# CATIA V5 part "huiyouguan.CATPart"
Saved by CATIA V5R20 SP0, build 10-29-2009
Part number: huiyouguan
Material "无"
Bounding box of the stored display mesh (mm): x -24.924 to 17.931, y -271.713 to -24.431, z -40.483 to -8.901
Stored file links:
  C:\Users\Administrator\Desktop\huiyouguan.CATPart
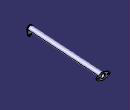
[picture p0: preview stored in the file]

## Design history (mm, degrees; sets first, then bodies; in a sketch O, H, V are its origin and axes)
Body1 (main body), material "无"
  DatumSurface1
  DatumCurve1 to DatumCurve3
  Sketch1 on face of DatumSurface1, origin (-1.5922, -25.6122, 0), H (-0.9981, 0.062, 0), V (0, 0, 1)
    projected circle E1 centre (-13.718, -19.4994) radius 3.1606 from edge of DatumCurve1
    projected circle E2 centre (13.2753, -19.4994) radius 3.1606 from edge of DatumCurve2
    projected circle E3 centre (-0.8655, -19.0792) radius 6.8742 from edge of DatumCurve3
    point P1 (-0.8655, -19.0792)
    point P2 (-13.718, -19.4994)
    point P3 (13.2753, -19.4994)
    arc A1 centre (-0.8655, -19.0792) radius 10.1979 from (1.5838, -9.1798) to (-4.5193, -9.5584) ccw
    arc A2 centre (-13.718, -19.4994) radius 5.9852 from (-15.8625, -13.9115) to (-16.0663, -25.0048) ccw
    arc A3 centre (13.2753, -19.4994) radius 5.9056 from (14.8682, -25.1861) to (15.2155, -13.9217) ccw
    line L1 (-4.5193, -9.5584) -> (-15.8625, -13.9115)
    line L2 (-16.0663, -25.0048) -> (-4.2992, -28.6816)
    line L3 (3.0428, -28.4984) -> (14.8682, -25.1861)
    line L4 (1.5838, -9.1798) -> (15.2155, -13.9217)
    arc A4 centre (-0.8655, -19.0792) radius 10.1979 from (-4.2992, -28.6816) to (3.0428, -28.4984) ccw
    concentricity: P1 E3, P2 E1, P3 E2
    tangency: A2 E3, L1 A2, L3 A3, L4 A3, L1 A1
  Pad1: profile Sketch1, direction (-0.062, -0.9981, 0), length 3
  DatumCurve4
  Sketch2 on end face of Pad1, origin (-1.7784, -28.6064, 0), H (0.9981, -0.062, 0), V (0, 0, 1)
    circle A1 centre (0.8655, -19.0792) radius 7.1478
    reference projected circle E1 centre (0.8655, -19.0792) radius 4.8742 from edge of DatumCurve4
    circle A2 centre (0.8655, -19.0792) radius 6.4128
    concentricity: A1 E1
  Pad2: profile Sketch2, direction (-0.062, -0.9981, 0), length 240
  Fillet1: radius 0.3, on end face of Pad1
  Sketch3 on end face of Pad2, origin (-16.6697, -268.144, 0), H (0.9981, -0.062, 0), V (0, 0, 1)
    projected circle E1 centre (0.8655, -19.0792) radius 7.1478 from edge [face of Pad2 from Sketch2.A1 | end face of Pad2]
    arc A1 centre (0.8655, -19.0792) radius 9 from (9.7651, -20.4197) to (-7.6301, -22.0498) ccw
    line L1 (9.7651, -20.4197) -> (7.3761, -36.2803)
    line L2 (-7.6301, -22.0498) -> (-2.3361, -37.1905)
    arc A2 centre (2.4073, -35.5319) radius 5.0249 from (-2.3361, -37.1905) to (7.3761, -36.2803) ccw
    circle A3 centre (2.4073, -35.5319) radius 2.3025
    radius A1 = 9
    tangency: L1 A1, L2 A1, A2 L2, A2 L1
  Pad3: profile Sketch3, direction (-0.062, -0.9981, 0), length 3
  Fillet2: radius 0.5, on end face of Pad3; start face of Pad3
